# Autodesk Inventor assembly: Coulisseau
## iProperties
Author: Flavien MARTY
Shininess: 21.0
PropertySet Name: _Private Model Information
Created: 2001-10
Part Number: Coulisseau
Document SubType Name: Assemblage
Designer: Flavien MARTY
Control State: 0
Master: False
Checked Out: False
PropertySet Name: Design Tracking Control
Density: 0.0
Volumn: 0.0
Area: 0.0
PropertySet Name: Model Information
